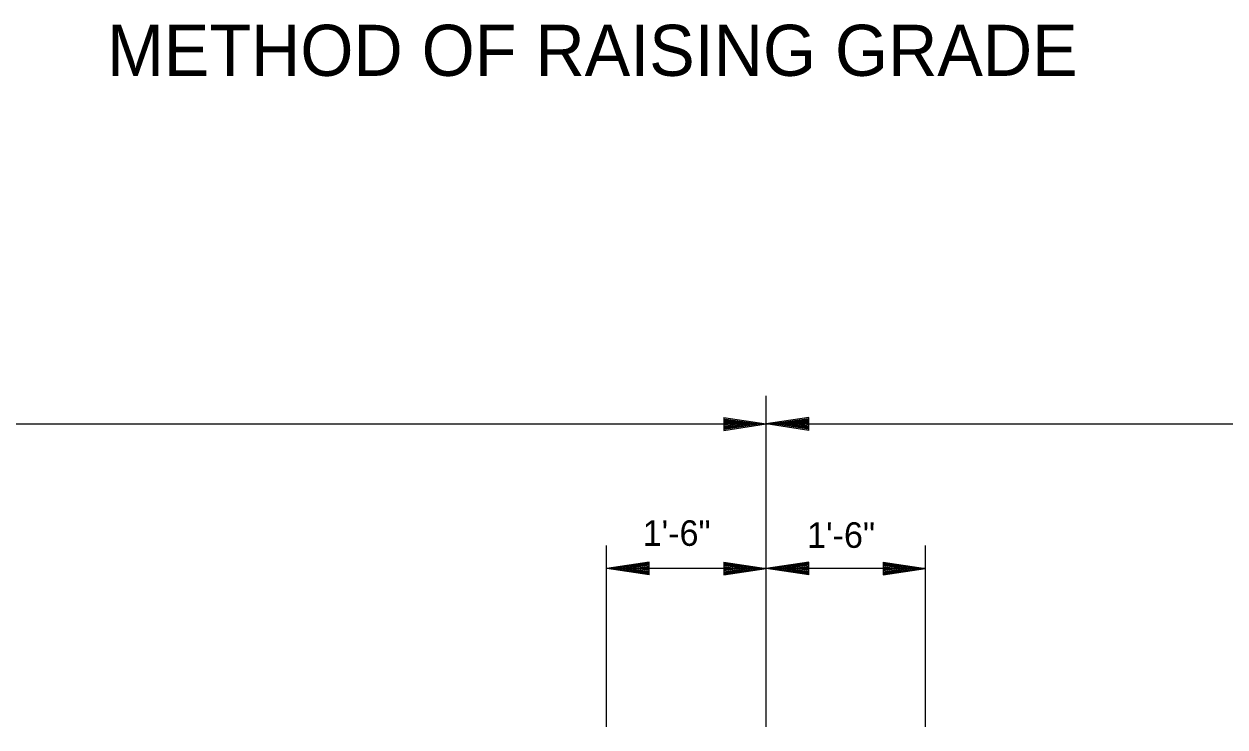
# Model space of a CAD drawing. Extents: x 634177 to 635904, y 289936 to 290970.
# Drawn here: x 635698.57 to 635726.81, y 290579.45 to 290595.97 of the extents above; entities that cross this region are included whole.
import ezdxf

# ---------------------------------------------------------------- set-up
doc = ezdxf.new("R2010")
doc.units = 0
doc.layers.add('Default', color=7, linetype='Continuous')

msp = doc.modelspace()

# ---------------------------------------------------------------- linework, layer by layer
at = {"layer": 'Default'}
for p, q in [((635716.022, 290579.454), (635716.022, 290587.235)), ((635666.025, 290586.573), (635716.022, 290586.573)), ((635715.024, 290586.723), (635716.024, 290586.573)), ((635715.024, 290586.723), (635715.024, 290586.423)), ((635715.024, 290586.698), (635715.856, 290586.573)), ((635715.024, 290586.673), (635715.684, 290586.573)), ((635715.024, 290586.648), (635715.519, 290586.573)), ((635715.024, 290586.623), (635715.349, 290586.573)), ((635715.024, 290586.598), (635715.181, 290586.573)), ((635715.024, 290586.423), (635716.024, 290586.573)), ((635715.024, 290586.525), (635715.349, 290586.573)), ((635715.024, 290586.473), (635715.684, 290586.573)), ((635715.024, 290586.448), (635715.856, 290586.573)), ((635715.024, 290586.498), (635715.519, 290586.573)), ((635715.024, 290586.55), (635715.181, 290586.573)), ((635716.022, 290586.573), (635757.27, 290586.573)), ((635717.023, 290586.723), (635716.024, 290586.573)), ((635717.023, 290586.423), (635716.024, 290586.573)), ((635717.023, 290586.698), (635716.191, 290586.573)), ((635717.023, 290586.448), (635716.191, 290586.573)), ((635717.023, 290586.673), (635716.361, 290586.573)), ((635717.023, 290586.473), (635716.361, 290586.573)), ((635717.023, 290586.648), (635716.528, 290586.573)), ((635717.023, 290586.498), (635716.528, 290586.573)), ((635717.023, 290586.623), (635716.698, 290586.573)), ((635717.023, 290586.525), (635716.698, 290586.573)), ((635717.023, 290586.598), (635716.866, 290586.573)), ((635717.023, 290586.55), (635716.866, 290586.573)), ((635717.023, 290586.423), (635717.023, 290586.723)), ((635712.272, 290579.454), (635712.272, 290583.717)), ((635719.772, 290579.454), (635719.772, 290583.717)), ((635716.022, 290583.178), (635712.272, 290583.178)), ((635713.274, 290583.328), (635712.274, 290583.178)), ((635713.274, 290583.303), (635712.441, 290583.178)), ((635713.274, 290583.278), (635712.611, 290583.178)), ((635713.274, 290583.253), (635712.779, 290583.178)), ((635713.274, 290583.228), (635712.949, 290583.178)), ((635713.274, 290583.203), (635713.116, 290583.178)), ((635713.274, 290583.028), (635713.274, 290583.328)), ((635715.024, 290583.328), (635716.024, 290583.178)), ((635715.024, 290583.328), (635715.024, 290583.028)), ((635715.024, 290583.303), (635715.856, 290583.178)), ((635715.024, 290583.278), (635715.684, 290583.178)), ((635715.024, 290583.253), (635715.519, 290583.178)), ((635715.024, 290583.228), (635715.349, 290583.178)), ((635715.024, 290583.203), (635715.181, 290583.178)), ((635719.772, 290583.178), (635716.022, 290583.178)), ((635717.023, 290583.328), (635716.024, 290583.178)), ((635717.023, 290583.303), (635716.191, 290583.178)), ((635717.023, 290583.278), (635716.361, 290583.178)), ((635717.023, 290583.253), (635716.528, 290583.178)), ((635717.023, 290583.228), (635716.698, 290583.178)), ((635717.023, 290583.203), (635716.866, 290583.178)), ((635717.023, 290583.028), (635717.023, 290583.328)), ((635718.773, 290583.328), (635719.773, 290583.178)), ((635718.773, 290583.328), (635718.773, 290583.028)), ((635718.773, 290583.303), (635719.606, 290583.178)), ((635718.773, 290583.278), (635719.433, 290583.178)), ((635718.773, 290583.253), (635719.268, 290583.178)), ((635718.773, 290583.228), (635719.098, 290583.178)), ((635718.773, 290583.203), (635718.931, 290583.178)), ((635713.274, 290583.028), (635712.274, 290583.178)), ((635713.274, 290583.053), (635712.441, 290583.178)), ((635713.274, 290583.078), (635712.611, 290583.178)), ((635713.274, 290583.103), (635712.779, 290583.178)), ((635713.274, 290583.13), (635712.949, 290583.178)), ((635713.274, 290583.155), (635713.116, 290583.178)), ((635715.024, 290583.028), (635716.024, 290583.178)), ((635715.024, 290583.13), (635715.349, 290583.178)), ((635715.024, 290583.078), (635715.684, 290583.178)), ((635715.024, 290583.053), (635715.856, 290583.178)), ((635715.024, 290583.103), (635715.519, 290583.178)), ((635715.024, 290583.155), (635715.181, 290583.178)), ((635717.023, 290583.028), (635716.024, 290583.178)), ((635717.023, 290583.053), (635716.191, 290583.178)), ((635717.023, 290583.078), (635716.361, 290583.178)), ((635717.023, 290583.103), (635716.528, 290583.178)), ((635717.023, 290583.13), (635716.698, 290583.178)), ((635717.023, 290583.155), (635716.866, 290583.178)), ((635718.773, 290583.028), (635719.773, 290583.178)), ((635718.773, 290583.13), (635719.098, 290583.178)), ((635718.773, 290583.078), (635719.433, 290583.178)), ((635718.773, 290583.053), (635719.606, 290583.178)), ((635718.773, 290583.103), (635719.268, 290583.178)), ((635718.773, 290583.155), (635718.931, 290583.178))]:
    msp.add_line(p, q, dxfattribs=at)

# ---------------------------------------------------------------- texts
for s, height, p in [('METHOD OF RAISING GRADE', 1.2, (635700.524, 290594.753)), ('1\'-6"', 0.6, (635713.119, 290583.71)), ('1\'-6"', 0.6, (635716.986, 290583.663))]:
    msp.add_text(s, height=height, dxfattribs=at).set_placement(p)

doc.saveas('drawing.dxf')
